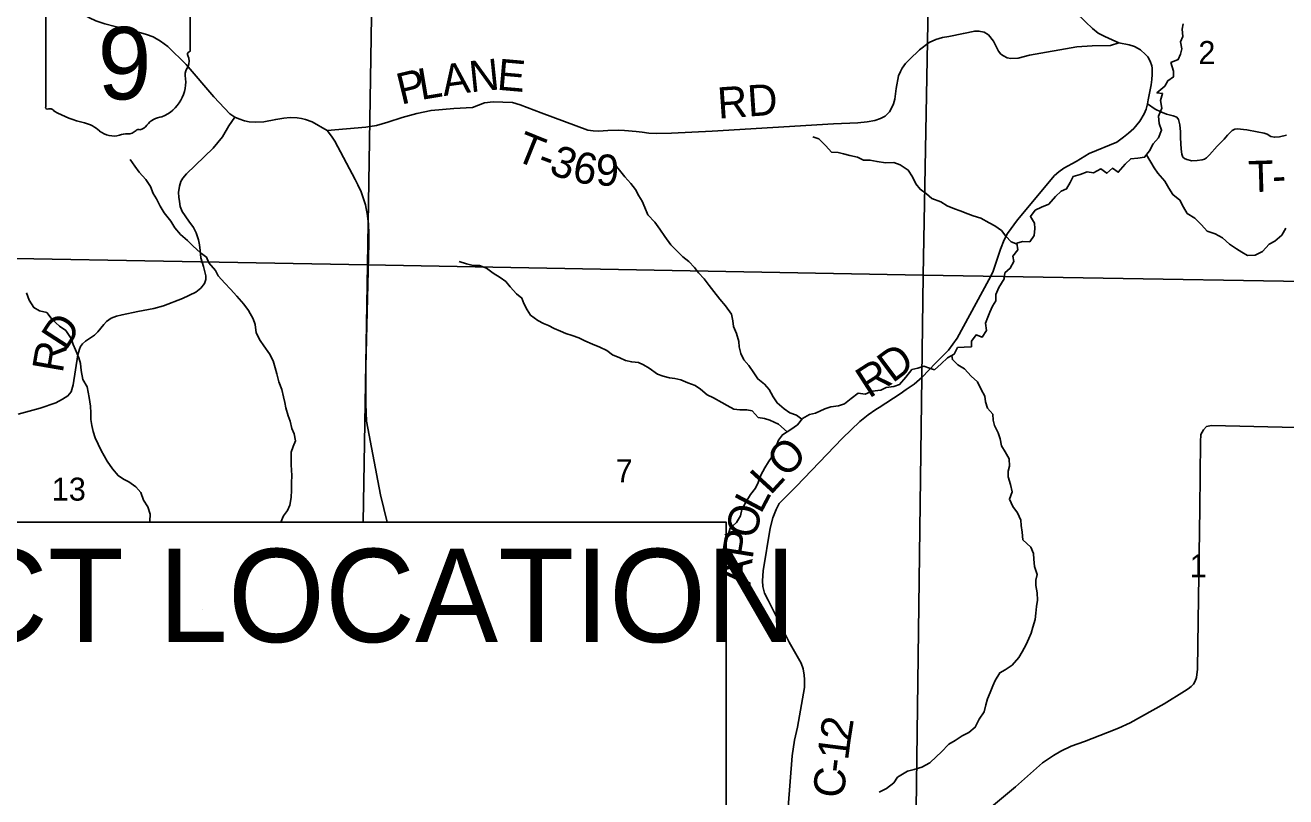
# Model space of a CAD drawing. Extents: x -20.5 to 34, y -66 to 23.9.
# Drawn here: x 3.275 to 5.573, y 17.524 to 18.93 of the extents above; entities that cross this region are included whole.
import ezdxf

# ---------------------------------------------------------------- set-up
doc = ezdxf.new("R2010")
doc.units = 0
for name, color, linetype in [('GM_X_County_Text', 7, 'Continuous'), ('GM_X_Minor_Lake', 7, 'Continuous'), ('GM_X_Minor_River_Text', 7, 'Continuous'), ('GM_X_Section_Text', 7, 'Continuous'), ('GM_X_State_Route', 7, 'Continuous'), ('GM_X_Township_Road', 7, 'Continuous'), ('GM_X_Township_Road_Text', 7, 'Continuous'), ('GM_X_Township_Text', 7, 'Continuous'), ('GM_X_Unincorporated', 7, 'Continuous'), ('GM_X_Unincorporated_Location', 7, 'Continuous'), ('SH_Text', 7, 'Continuous')]:
    doc.layers.add(name, color=color, linetype=linetype)

msp = doc.modelspace()

# ---------------------------------------------------------------- linework, layer by layer
at = {"layer": 'GM_X_County_Text'}
for points in [[(3.8249, 18.738), (3.8956, 18.7439), (3.915, 18.7471), (3.9356, 18.7534), (3.9619, 18.7619), (3.9883, 18.7692), (4.0144, 18.7746), (4.056, 18.7782), (4.0901, 18.78), (4.1118, 18.7885), (4.1275, 18.7904), (4.1629, 18.7889), (4.177, 18.7847), (4.2155, 18.7703), (4.3003, 18.7384), (4.3099, 18.7371), (4.3195, 18.7367), (4.3366, 18.7381), (4.3558, 18.7383), (4.3671, 18.7378), (4.3883, 18.736), (4.3996, 18.7351), (4.4114, 18.7332), (4.4248, 18.7323), (4.4525, 18.7333), (4.5269, 18.7369), (4.7478, 18.7504), (4.7926, 18.7522), (4.8096, 18.7538), (4.8236, 18.7561), (4.834, 18.7599), (4.8423, 18.7641), (4.85, 18.7722), (4.8537, 18.7788), (4.8574, 18.7864), (4.8601, 18.7953), (4.8624, 18.8142), (4.8667, 18.8375), (4.8702, 18.8455), (4.8735, 18.8517), (4.8793, 18.8599), (4.8865, 18.8673), (4.9046, 18.8848), (4.9223, 18.898), (4.9344, 18.9038), (4.9469, 18.9073), (4.9586, 18.9095), (4.985, 18.9149), (5.0057, 18.919), (5.0132, 18.9191), (5.0227, 18.9169), (5.0305, 18.912), (5.0395, 18.9006), (5.0488, 18.8823), (5.0532, 18.8773), (5.0582, 18.8742), (5.0647, 18.8704), (5.0714, 18.869), (5.0849, 18.87), (5.1054, 18.8755), (5.1918, 18.8904), (5.2195, 18.8925), (5.2529, 18.8929), (5.2682, 18.8977)], [(5.2682, 18.8977), (5.2873, 18.894), (5.297, 18.8908), (5.3075, 18.885), (5.317, 18.8765), (5.3209, 18.8722), (5.3254, 18.8643), (5.3284, 18.856), (5.3291, 18.8515), (5.3293, 18.8398), (5.3284, 18.8306), (5.3273, 18.8214), (5.3218, 18.7937), (5.3204, 18.7866)], [(5.3204, 18.7866), (5.3342, 18.7771), (5.3448, 18.7718), (5.355, 18.7677), (5.3675, 18.7646), (5.3738, 18.7623), (5.3771, 18.7583), (5.3797, 18.748), (5.3807, 18.7354), (5.3804, 18.7246), (5.3819, 18.7039), (5.3828, 18.6951), (5.3848, 18.6896), (5.3877, 18.6869), (5.3919, 18.6854), (5.4012, 18.683), (5.4109, 18.6833), (5.4203, 18.6844), (5.4246, 18.6856), (5.4282, 18.6881), (5.4337, 18.6936), (5.4472, 18.7096), (5.4601, 18.7223), (5.4663, 18.7292), (5.4747, 18.738), (5.4798, 18.7404), (5.484, 18.7412), (5.5013, 18.7392), (5.5207, 18.7354), (5.5332, 18.7331), (5.5388, 18.7314), (5.5456, 18.7269), (5.552, 18.7257), (5.5609, 18.7262), (5.5738, 18.7296)], [(3.2619, 18.2211), (3.3017, 18.2323), (3.3305, 18.242), (3.3427, 18.2483), (3.3526, 18.2544), (3.3587, 18.2619), (3.3618, 18.2745), (3.3705, 18.3291), (3.3738, 18.3396), (3.3752, 18.3446), (3.3789, 18.3495), (3.3843, 18.3544), (3.3916, 18.3589), (3.4007, 18.3652), (3.4073, 18.3715), (3.4179, 18.3844), (3.423, 18.3903), (3.4311, 18.396), (3.4408, 18.3997), (3.4513, 18.4022), (3.48, 18.4082), (3.5089, 18.414), (3.527, 18.4183), (3.5612, 18.432), (3.5858, 18.4432), (3.5948, 18.451), (3.6013, 18.459), (3.6041, 18.4664), (3.604, 18.4731), (3.5994, 18.4901), (3.5951, 18.5062), (3.5938, 18.5191), (3.5924, 18.5294), (3.5908, 18.5389), (3.5865, 18.5513), (3.5817, 18.5611), (3.5729, 18.5728), (3.5609, 18.5904), (3.5574, 18.5995), (3.5557, 18.6085), (3.5549, 18.6165), (3.5542, 18.625), (3.5558, 18.6366), (3.5584, 18.6451), (3.562, 18.651), (3.5684, 18.6588), (3.6175, 18.7056), (3.6346, 18.7262), (3.6458, 18.7463), (3.6569, 18.7622)], [(3.6569, 18.7622), (3.6641, 18.7591), (3.6745, 18.7556), (3.683, 18.7538), (3.6944, 18.7531), (3.7094, 18.7539), (3.7315, 18.7581), (3.7462, 18.7605), (3.7576, 18.7614), (3.7704, 18.7612), (3.7781, 18.7599), (3.7858, 18.7583), (3.7979, 18.7538), (3.8249, 18.738)]]:
    msp.add_lwpolyline(points, dxfattribs=at)
at = {"layer": 'GM_X_Minor_Lake'}
for points in [[(3.9151, 19.5111), (3.8987, 18.493), (2.8841, 18.5113), (2.9013, 19.5268)], [(3.9151, 19.5111), (4.9304, 19.491), (4.9118, 18.4742), (3.8987, 18.493)], [(4.9304, 19.491), (5.9508, 19.4767), (5.9493, 19.3913), (5.9332, 18.4574), (4.9118, 18.4742)], [(4.9118, 18.4742), (5.9332, 18.4574), (5.9313, 18.3709), (5.9103, 17.4412), (4.9246, 17.4548), (4.898, 17.4556)]]:
    msp.add_lwpolyline(points, close=True, dxfattribs=at)
for points in [[(2.8799, 18.0245), (2.8841, 18.5113), (3.8987, 18.493), (3.8907, 18.0245)], [(3.8907, 18.0245), (3.8987, 18.493), (4.9118, 18.4742), (4.898, 17.4556), (4.5524, 17.4637)]]:
    msp.add_lwpolyline(points, dxfattribs=at)
at = {"layer": 'GM_X_Minor_River_Text'}
msp.add_line((3.5986, 17.8652), (3.5986, 17.8652), dxfattribs=at)
for points in [[(4.9325, 18.302), (4.9441, 18.313), (4.956, 18.3238), (4.968, 18.3304), (4.9743, 18.3426), (4.986, 18.3432), (4.9996, 18.3441), (4.9994, 18.3544), (5.008, 18.3655), (5.0194, 18.3615), (5.0272, 18.3738), (5.0254, 18.387), (5.0294, 18.3977), (5.0331, 18.4072), (5.0378, 18.4179), (5.0441, 18.4275), (5.0443, 18.4393), (5.0494, 18.4522), (5.059, 18.4679), (5.0607, 18.4786), (5.0704, 18.4871), (5.0771, 18.4993), (5.075, 18.5091), (5.0843, 18.5207), (5.0826, 18.5328), (5.0928, 18.5356), (5.1057, 18.535), (5.1138, 18.5465), (5.1151, 18.5594), (5.1146, 18.5693), (5.1072, 18.5813), (5.1158, 18.5928), (5.127, 18.5983), (5.1406, 18.6038), (5.1525, 18.6177), (5.1629, 18.6277), (5.1731, 18.632), (5.1793, 18.6435), (5.1848, 18.6542), (5.198, 18.6578), (5.2104, 18.6626), (5.2222, 18.6608), (5.2357, 18.6679), (5.2464, 18.6601), (5.2565, 18.6693), (5.2672, 18.6619), (5.2798, 18.6765), (5.2899, 18.6865), (5.3028, 18.6875), (5.3152, 18.6892), (5.3241, 18.7011), (5.3307, 18.7137), (5.3404, 18.7248), (5.3462, 18.7386), (5.3415, 18.751), (5.3406, 18.7639), (5.3464, 18.7788), (5.3443, 18.7924), (5.3479, 18.8054), (5.3376, 18.8064), (5.3518, 18.8187), (5.3577, 18.8287), (5.3678, 18.8356), (5.3677, 18.8459), (5.3633, 18.8617), (5.3764, 18.8673), (5.3808, 18.8768), (5.383, 18.8867), (5.3809, 18.8996), (5.3849, 18.9091), (5.3839, 18.9227), (5.3853, 18.9322)], [(4.9273, 18.6143), (4.9174, 18.6224), (4.9059, 18.631), (4.8982, 18.6407), (4.8923, 18.6535), (4.8845, 18.6658), (4.8699, 18.6755), (4.8578, 18.6794), (4.843, 18.6788), (4.8274, 18.6812), (4.8145, 18.684), (4.8028, 18.6842), (4.7917, 18.6893), (4.778, 18.6925), (4.7663, 18.6957), (4.7568, 18.6978), (4.7442, 18.6987), (4.7342, 18.7099), (4.7211, 18.7229), (4.7105, 18.7265)], [(3.7648, 18.1854), (3.7608, 18.1952), (3.7579, 18.2084), (3.754, 18.2182), (3.7496, 18.2325), (3.7479, 18.2424), (3.7458, 18.2526), (3.7426, 18.2661), (3.737, 18.2801), (3.7334, 18.2948), (3.7305, 18.3057), (3.7269, 18.3186), (3.7202, 18.3313), (3.7098, 18.3459), (3.7032, 18.3557), (3.6957, 18.3696), (3.6936, 18.3847), (3.6904, 18.3949), (3.6814, 18.4099), (3.6732, 18.4215), (3.6605, 18.4364), (3.6486, 18.4487), (3.6385, 18.46), (3.6266, 18.473), (3.6218, 18.4828), (3.6095, 18.497), (3.6051, 18.5071), (3.5944, 18.5153), (3.5802, 18.5279), (3.5706, 18.5376), (3.5579, 18.5484), (3.5474, 18.5604), (3.54, 18.5727), (3.5281, 18.5877), (3.5206, 18.6001), (3.514, 18.6132), (3.5081, 18.623), (3.503, 18.6362), (3.4944, 18.6485), (3.4825, 18.662), (3.4743, 18.6732), (3.4658, 18.6852)], [(5.3186, 18.6938), (5.3325, 18.6697), (5.3391, 18.66), (5.3518, 18.6457), (5.3596, 18.633), (5.3666, 18.6213), (5.3796, 18.6113), (5.3859, 18.5985), (5.3925, 18.5868), (5.407, 18.5783), (5.4189, 18.5664), (5.4293, 18.5548), (5.4437, 18.55), (5.4571, 18.5427), (5.4701, 18.5311), (5.4828, 18.5222), (5.4923, 18.5163), (5.5026, 18.5104), (5.517, 18.511), (5.5301, 18.5176), (5.5424, 18.5307), (5.5525, 18.5365), (5.5652, 18.5474), (5.5726, 18.56)], [(4.6906, 18.2119), (4.6806, 18.2193), (4.6684, 18.2236), (4.6584, 18.231), (4.6454, 18.2418), (4.638, 18.253), (4.6306, 18.2662), (4.6221, 18.2759), (4.6102, 18.2855), (4.6028, 18.2968), (4.5935, 18.3099), (4.5846, 18.32), (4.5791, 18.3316), (4.5759, 18.3441), (4.5757, 18.3535), (4.5713, 18.3679), (4.5658, 18.381), (4.5645, 18.3913), (4.5624, 18.4033), (4.5511, 18.4187), (4.5407, 18.431), (4.5298, 18.4445), (4.5217, 18.4557), (4.5124, 18.4677), (4.502, 18.4785), (4.4946, 18.4886), (4.4842, 18.4994), (4.4735, 18.5076), (4.4639, 18.5173), (4.4515, 18.5299), (4.4407, 18.5449), (4.4317, 18.558), (4.4224, 18.5708), (4.4097, 18.5842), (4.4042, 18.5974), (4.3994, 18.609), (4.3932, 18.6188), (4.387, 18.6304), (4.3788, 18.6413), (4.3676, 18.6536), (4.358, 18.6659), (4.3467, 18.6798)], [(5.0829, 18.5308), (5.072, 18.5349), (5.0624, 18.5454), (5.0543, 18.5555), (5.042, 18.564), (5.0317, 18.5699), (5.0168, 18.5784), (5.0028, 18.5828), (4.9929, 18.5864), (4.9788, 18.5915), (4.9689, 18.5955), (4.9556, 18.6006), (4.9437, 18.608), (4.9273, 18.6143)], [(4.6638, 18.1891), (4.6476, 18.2032), (4.6323, 18.2105), (4.6224, 18.2133), (4.611, 18.2154), (4.5998, 18.227), (4.5903, 18.2291), (4.5775, 18.2293), (4.5665, 18.2302), (4.5542, 18.2372), (4.5443, 18.2423), (4.5294, 18.2508), (4.518, 18.2563), (4.5057, 18.2667), (4.4957, 18.2733), (4.4828, 18.278), (4.4698, 18.2835), (4.4588, 18.286), (4.4493, 18.2873), (4.4375, 18.2902), (4.4272, 18.2938), (4.4119, 18.3049), (4.4019, 18.3108), (4.3924, 18.3152), (4.3803, 18.3165), (4.3692, 18.3189), (4.3586, 18.3241), (4.3452, 18.3295), (4.3349, 18.3369), (4.3223, 18.3431), (4.3085, 18.3486), (4.2948, 18.3548), (4.2837, 18.3603), (4.2716, 18.3646), (4.2601, 18.3679), (4.2502, 18.3726), (4.2388, 18.3773), (4.2288, 18.3825), (4.2193, 18.3865), (4.2094, 18.3916), (4.196, 18.4016), (4.1894, 18.4114), (4.1839, 18.4227), (4.1799, 18.4328), (4.1703, 18.4406), (4.1584, 18.4529), (4.151, 18.4626), (4.1406, 18.4704), (4.1276, 18.4782), (4.1154, 18.4871), (4.1028, 18.4921), (4.0911, 18.4923), (4.0793, 18.4948), (4.0656, 18.4991)], [(3.5022, 18.0245), (3.5018, 18.0263), (3.5023, 18.0392), (3.4979, 18.0527), (3.4905, 18.0644), (3.4857, 18.0783), (3.4761, 18.0891), (3.4634, 18.098), (3.4539, 18.1031), (3.4439, 18.1094), (3.4335, 18.1214), (3.4242, 18.1356), (3.4133, 18.1551), (3.4074, 18.1668), (3.4019, 18.1781), (3.3987, 18.1894), (3.3962, 18.2003), (3.3941, 18.2113), (3.3943, 18.2234), (3.3937, 18.2355), (3.3911, 18.2514), (3.3878, 18.2711), (3.3796, 18.2842), (3.3767, 18.3008), (3.3757, 18.3137), (3.3725, 18.3239), (3.3666, 18.3386), (3.3622, 18.3483), (3.3582, 18.3593), (3.3485, 18.3739), (3.337, 18.3816), (3.3236, 18.3939), (3.3139, 18.4063), (3.3006, 18.4094), (3.2903, 18.4153), (3.2821, 18.4288), (3.2773, 18.442)], [(4.964, 18.3281), (4.9648, 18.3205), (4.9748, 18.3108), (4.987, 18.3041), (4.9993, 18.2903), (5.0108, 18.2802), (5.0174, 18.2663), (5.0241, 18.2539), (5.025, 18.2436), (5.0289, 18.2323), (5.0386, 18.2211), (5.0391, 18.2105), (5.0415, 18.2006), (5.0482, 18.1871), (5.0521, 18.1762), (5.0546, 18.1637), (5.0612, 18.1524), (5.0682, 18.1396), (5.0688, 18.1267), (5.0663, 18.1172), (5.0664, 18.1073), (5.0708, 18.093), (5.074, 18.0798), (5.0689, 18.0664), (5.0748, 18.0528), (5.0837, 18.0416), (5.0896, 18.0284), (5.0905, 18.0182), (5.0918, 18.0065), (5.0935, 17.9925), (5.1077, 17.979), (5.1128, 17.9677), (5.113, 17.9571), (5.1143, 17.9438), (5.1191, 17.9291), (5.117, 17.9188), (5.1171, 17.9094), (5.1192, 17.8957), (5.1198, 17.8825), (5.1181, 17.8711), (5.1171, 17.8589), (5.1158, 17.8471), (5.1115, 17.833), (5.1086, 17.822), (5.1042, 17.8124), (5.0991, 17.8017), (5.0921, 17.788), (5.0862, 17.7777), (5.0736, 17.7642), (5.0612, 17.7557), (5.0515, 17.7502), (5.043, 17.736), (5.0386, 17.7261), (5.0338, 17.7139), (5.0291, 17.7024), (5.0255, 17.6918), (5.0227, 17.6788), (5.0138, 17.6658), (5.0064, 17.6509), (4.9948, 17.6416), (4.9825, 17.635), (4.9701, 17.6268), (4.9581, 17.6202), (4.9442, 17.6056)], [(4.9325, 18.302), (4.9233, 18.3053), (4.9126, 18.3085), (4.9021, 18.3053), (4.8911, 18.3025), (4.88, 18.2886), (4.8685, 18.2755), (4.858, 18.2716), (4.8444, 18.2698), (4.8343, 18.2647), (4.8188, 18.2629), (4.806, 18.2574), (4.7931, 18.2595), (4.7804, 18.2498), (4.7684, 18.2401), (4.7572, 18.2361), (4.7432, 18.2344), (4.7323, 18.2311), (4.7154, 18.2233), (4.7041, 18.2204), (4.6917, 18.2134), (4.6824, 18.2015), (4.6704, 18.1933), (4.6551, 18.1836), (4.6481, 18.174), (4.6408, 18.1549), (4.6361, 18.1442), (4.6295, 18.1342), (4.6228, 18.1235), (4.6155, 18.1098), (4.6108, 18.0968), (4.6061, 18.0865), (4.5968, 18.0746), (4.5883, 18.0611), (4.581, 18.0478), (4.5785, 18.0363), (4.5712, 18.0241), (4.56, 18.0133), (4.5568, 18.003), (4.5501, 18.0014)], [(3.7406, 18.0245), (3.7458, 18.0361), (3.7528, 18.0457), (3.7572, 18.0553), (3.7592, 18.0693), (3.7601, 18.083), (3.7599, 18.0959), (3.7604, 18.1095), (3.7602, 18.1194), (3.7597, 18.1292), (3.7594, 18.1425), (3.7597, 18.152), (3.7633, 18.1626), (3.7673, 18.1726), (3.7648, 18.1854)], [(4.9442, 17.6056), (4.9359, 17.5978), (4.9239, 17.5863), (4.9093, 17.5781), (4.895, 17.574), (4.8829, 17.5708), (4.8646, 17.5599), (4.8579, 17.5499), (4.8449, 17.5394), (4.8314, 17.5328)]]:
    msp.add_lwpolyline(points, dxfattribs=at)
at = {"layer": 'GM_X_State_Route'}
for points in [[(5.2682, 18.8977), (5.2559, 18.9034), (5.2425, 18.9094), (5.2307, 18.9155), (5.22, 18.9235), (5.2074, 18.9357), (5.1986, 18.9451), (5.1975, 18.9467)], [(5.3204, 18.7866), (5.3218, 18.7937), (5.3273, 18.8214), (5.3284, 18.8306), (5.3293, 18.8398), (5.3291, 18.8515), (5.3284, 18.856), (5.3254, 18.8643), (5.3209, 18.8722), (5.317, 18.8765), (5.3075, 18.885), (5.297, 18.8908), (5.2873, 18.894), (5.2682, 18.8977)], [(4.6657, 17.5056), (4.673, 17.5988), (4.6773, 17.6271), (4.6825, 17.651), (4.695, 17.7232), (4.6955, 17.7376), (4.6946, 17.746), (4.6929, 17.7575), (4.6894, 17.7675), (4.6869, 17.7721), (4.6674, 17.806), (4.6293, 17.8824), (4.6224, 17.8952), (4.6193, 17.9074), (4.6189, 17.9174), (4.6199, 17.9357), (4.6326, 18.0138), (4.6376, 18.0321), (4.6401, 18.0386), (4.6438, 18.0478), (4.6492, 18.0583), (4.6799, 18.0894), (4.7648, 18.1772), (4.796, 18.2081), (4.811, 18.2201), (4.8252, 18.2297), (4.8312, 18.2335), (4.8695, 18.2582), (4.8805, 18.266), (4.8952, 18.2758), (4.9097, 18.2884), (4.9343, 18.3143), (4.9576, 18.3378), (4.9737, 18.3595), (5.0314, 18.4662), (5.0383, 18.4796), (5.0525, 18.5218), (5.059, 18.5385), (5.0654, 18.5506), (5.0833, 18.575), (5.151, 18.656), (5.1589, 18.6628), (5.1679, 18.6691), (5.1906, 18.6812), (5.214, 18.6959), (5.2645, 18.7167), (5.2769, 18.7257), (5.2857, 18.7332), (5.2955, 18.7419), (5.3066, 18.7549), (5.3146, 18.7686), (5.318, 18.7768), (5.3204, 18.7866)], [(5.746, 18.1933), (5.4374, 18.2004), (5.4283, 18.199), (5.4226, 18.1928), (5.4177, 18.1843), (5.4174, 18.1707), (5.4156, 18.0492), (5.4131, 17.845), (5.4114, 17.7569), (5.4097, 17.7415), (5.4075, 17.7346), (5.4042, 17.7296), (5.4003, 17.7252), (5.3949, 17.7206), (5.3882, 17.7166), (5.3507, 17.6934), (5.2887, 17.6587), (5.2679, 17.6491), (5.2476, 17.6415), (5.2057, 17.625), (5.1812, 17.6165), (5.1625, 17.6076), (5.149, 17.5995), (5.1293, 17.586), (5.0796, 17.5421), (5.0291, 17.5001)]]:
    msp.add_lwpolyline(points, dxfattribs=at)
at = {"layer": 'GM_X_Township_Road'}
for points in [[(3.6569, 18.7622), (3.6478, 18.7683), (3.6187, 18.7993), (3.5678, 18.8582), (3.5345, 18.891), (3.5213, 18.9008), (3.5078, 18.9084), (3.496, 18.9131), (3.4853, 18.9161), (3.4645, 18.9212), (3.4388, 18.9275), (3.4197, 18.9322), (3.4034, 18.9377), (3.3919, 18.9431), (3.3821, 18.9489), (3.3709, 18.9574), (3.363, 18.9658), (3.3568, 18.9737), (3.3446, 18.9905), (3.3334, 19.0098), (3.3161, 19.0363), (3.2459, 19.1458)], [(3.8249, 18.738), (3.7979, 18.7538), (3.7858, 18.7583), (3.7781, 18.7599), (3.7704, 18.7612), (3.7576, 18.7614), (3.7462, 18.7605), (3.7315, 18.7581), (3.7094, 18.7539), (3.6944, 18.7531), (3.683, 18.7538), (3.6745, 18.7556), (3.6641, 18.7591), (3.6569, 18.7622)], [(3.9345, 18.0245), (3.9224, 18.0743), (3.8971, 18.2085), (3.8954, 18.2394), (3.8954, 18.3073), (3.901, 18.5325), (3.9008, 18.5502), (3.9002, 18.5671), (3.8994, 18.5777), (3.8983, 18.5869), (3.8963, 18.5957), (3.8948, 18.6026), (3.8926, 18.6101), (3.8907, 18.6154), (3.8868, 18.626), (3.8812, 18.6392), (3.8759, 18.649), (3.8393, 18.7185), (3.8328, 18.7275), (3.8249, 18.738)]]:
    msp.add_lwpolyline(points, dxfattribs=at)
at = {"layer": 'GM_X_Unincorporated'}
for p, q in [((3.5756, 18.8844), (3.5756, 18.9891)), ((3.312, 18.9807), (3.312, 18.7806)), ((3.5756, 18.8844), (3.5756, 18.8844))]:
    msp.add_line(p, q, dxfattribs=at)
for centre, radius, start, end in [((3.575, 18.8767), 0.00454, 107.944, 210.337), ((3.5461, 18.8635), 0.0273, 340.033, 23.6496), ((3.5725, 18.884), 0.00314, 289.6038, 7.7341), ((3.5861, 18.8406), 0.0198, 136.8065, 186.9296), ((3.4974, 18.8273), 0.0699, 292.3089, 8.9858), ((3.315, 18.7801), 0.00308, 171.9584, 258.3066), ((3.3155, 18.8006), 0.0235, 267.339, 280.6039), ((3.3203, 18.769), 0.00848, 29.7484, 93.2717), ((3.4274, 18.9488), 0.2019, 240.4129, 257.1985), ((3.3672, 18.6907), 0.0632, 47.1842, 75.836), ((3.5269, 18.7244), 0.0383, 94.4031, 142.5768), ((3.4355, 18.768), 0.0401, 230.7004, 286.2918), ((3.4586, 18.6989), 0.0329, 85.6951, 111.2099), ((3.4616, 18.7531), 0.0214, 268.777, 315.5493), ((3.4809, 18.7337), 0.00601, 65.7517, 132.6484), ((3.4783, 18.7612), 0.0226, 282.8732, 323.2771)]:
    msp.add_arc(centre, radius, start, end, dxfattribs=at)
at = {"layer": 'SH_Text'}
msp.add_lwpolyline([(2.3813, 18.0245), (4.5524, 18.0245), (4.5524, 17.2409), (2.3813, 17.2409)], close=True, dxfattribs=at)

# ---------------------------------------------------------------- texts
at = {"layer": 'GM_X_Section_Text'}
for s, height, rotation, p in [('N', 0.0568, 5.8164, (4.0865, 18.8074)), ('E', 0.0568, 355.0097, (4.1334, 18.8124)), ('P', 0.0568, 13.7078, (3.9599, 18.7847)), ('L', 0.0568, 9.5152, (3.996, 18.7935)), ('A', 0.0568, 8.0255, (4.0376, 18.8005)), ('RD', 0.05682, 3.9458, (4.5383, 18.7595)), ('T', 0.0568, 338.0434, (4.1642, 18.6851)), ('3', 0.0568, 339.9091, (4.2273, 18.6603)), ('-', 0.0568, 339.5795, (4.2051, 18.6686)), ('6', 0.0568, 349.2245, (4.2699, 18.6456)), ('9', 0.0568, 358.2376, (4.314, 18.638)), ('T', 0.0568, 1.7424, (5.5051, 18.6255)), ('-', 0.0568, 3.0413, (5.549, 18.6269)), ('D', 0.0568, 57.0667, (3.3486, 18.3351)), ('R', 0.0568, 80.2184, (3.3429, 18.2948))]:
    msp.add_text(s, height=height, rotation=rotation, dxfattribs=at).set_placement(p)
at = {"layer": 'GM_X_Township_Road_Text'}
for s, rotation, p in [('D', 36.8671, (4.8558, 18.2768)), ('R', 32.6524, (4.8129, 18.249)), ('O', 45.5783, (4.6617, 18.1032)), ('L', 47.4539, (4.6333, 18.0722)), ('L', 62.1143, (4.6156, 18.0378)), ('O', 77.5233, (4.6062, 17.9927)), ('P', 80.9681, (4.6004, 17.9558)), ('A', 85.4637, (4.5966, 17.9071)), ('2', 81.0968, (4.7789, 17.6236)), ('1', 82.6265, (4.7745, 17.5893)), ('-', 83.0827, (4.7717, 17.5663)), ('C', 83.2047, (4.7662, 17.52))]:
    msp.add_text(s, height=0.0568, rotation=rotation, dxfattribs=at).set_placement(p)
at = {"layer": 'GM_X_Township_Text'}
for s, height, p in [('2', 0.0419, (5.4131, 18.8591)), ('7', 0.0419, (4.3509, 18.0971)), ('13', 0.04186, (3.323, 18.0637)), ('1', 0.0419, (5.3973, 17.9242))]:
    msp.add_text(s, height=height, rotation=0, dxfattribs=at).set_placement(p)
at = {"layer": 'GM_X_Unincorporated'}
msp.add_text('9', height=0.1318, dxfattribs=at).set_placement((3.4067, 18.7947))
at = {"layer": 'GM_X_Unincorporated_Location'}
for s in ['s', 'r']:
    msp.add_text(s, height=0.000189, dxfattribs=at).set_placement((3.4408, 18.8673))
msp.add_text('9', height=0.000189, rotation=0, dxfattribs=at).set_placement((3.4123, 18.8536))
at = {"layer": 'SH_Text'}
msp.add_text('PROJECT LOCATION ', height=0.17, dxfattribs=at).set_placement((2.3937, 17.8059))

doc.saveas('drawing.dxf')
